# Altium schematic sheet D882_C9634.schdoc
size 127 x 101 mm
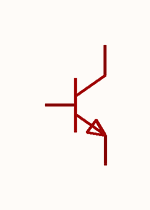
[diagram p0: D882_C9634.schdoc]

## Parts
Q?  d882(range:160-320)_c9634  [SOT-89-3_L4.5-W2.5-P1.50-LS4.2-BR]  (value not drawn)

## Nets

Not connected (* = marked no-connect by the designer): Q? 1(B) 2(C) 3(E)

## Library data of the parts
Q? = d882(range:160-320)_c9634: 晶体管类型:NPN;集电极电流(Ic):3A;集射极击穿电压(Vceo):30V;耗散功率(Pd):500mW;直流电流增益(hFE):160;; Manufacturer: CJ(江苏长电/长晶); Symbol: D882_C9634; AddInBom: yes; ModelId: 6db690b7897d4d18a30d90c1b89525ee; ModelName: SOT-89-3_L4.3-W2.5-H1.6-LS4.1-P1.50; ModelTransform: 161.417,169.291,0,180,0,0,-18.661,0,0; type: NPN; Current - Collector(Ic): 3A; Collector - Emitter Voltage VCEO: 30V; Pd - Power Dissipation: 500mW; DC Current Gain: 160; Transition frequency(fT): 50MHz; Current - Collector Cutoff: 1uA; Vce Saturation(VCE(sat)): 500mV; Emitter-Base Voltage(Vebo): 6V; Number: 1个NPN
